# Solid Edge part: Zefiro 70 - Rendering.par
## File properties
Title: Zefiro 70
Author: DESYS
Template: Normal.par
Last saved by: i.fialdini
Revision: 39
Application: Solid Edge
Tipo di contenuto documento: 0
Precisione: 0.990
Document Number: 8206
Revision: 0
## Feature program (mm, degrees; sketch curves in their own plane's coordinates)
lofted protrusion "unnamed LoftedProtrusion 1"
sketch for "unnamed Cutout 1" plane through (0, 0, 0) normal (1, 0, 0) x-axis (0, 1, 0)
  arc centre (0, 843.7224) radius 911.7224 from (-345.5, 0) to (345.5, 0) ccw
extrude "unnamed Cutout 1" cut through
thinwall "unnamed Thinwall 1"
sketch for "ExtrudedProtrusion_1" plane through (0, 0, -158) normal (0, 0, -1) x-axis (0, 1, 0)
extrude "ExtrudedProtrusion_1" add finite 10 along +normal
sketch for "ScavoEstrusione_2" plane through (0, 0, -168) normal (0, 0, -1) x-axis (0, 1, 0)
extrude "ScavoEstrusione_2" cut finite 15 along -normal
sketch for "ExtrudedProtrusion_6" plane through (-0.0005, 0, -153) normal (0, 0, -1) x-axis (0, 1, 0)
extrude "ExtrudedProtrusion_6" add finite 30 along +normal
sketch for "Foro_1" plane through (0, 0, -183) normal (0, 0, -1) x-axis (0, 1, 0)
  hole centre (0, 0) bore radius 25
hole "Foro_1" diameter 50 through
boolean "unnamed Boolean 1"
fillet "Rotondo_15" radius 10
fillet "Rotondo_1" radius 5
fillet "Rotondo_5" radius 10
fillet "Rotondo_3" radius 50
fillet "Rotondo_22" radius 40
fillet "Rotondo_23" radius 5
sketch for "unnamed RevolvedProtrusion 1" plane through (0, 0, 0) normal (1, 0, 0) x-axis (0, 1, 0)
revolve "unnamed RevolvedProtrusion 1" add full turn 360 deg
fillet "Rotondo_24" radius 5
fillet "Rotondo_25" radius 7
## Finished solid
Body 1: sheet body, 1 face, 2 edges, 0 vertices.
  Faces by surface: spline 1
  Edges by curve: circle 1, intersection 1
Body 2: solid body, 17 faces, 18 edges, 3 vertices.
  Faces by surface: blend 6, plane 4, cylinder 2, spline 2, cone 1, swept 1, torus 1
  Edges by curve: intersection 12, circle 5, ellipse 1
Bounding box of the edges (mm; curved faces can reach further): 357.510 x 680.842 x 178.409, from (-178.6113, -340.4187, -183) to (178.8991, 340.4235, -4.5911).
Cylindrical faces by radius (mm): R25 x1, R911.7224 x1
Conical faces (half-angle, radius in mm at the cone's reference point): 38.6598 deg R35 x1
Toroidal faces (ring radius, tube radius in mm): R30 r5 x1
Planar faces by outward normal: -z 4
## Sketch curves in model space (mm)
arc centre (25, 0, 23.7635) radius 171.7635 from (170.197, 0, -68) through (107.8887, 0, -126.6764) to (25, 0, -148)
arc centre (-25, 0, 23.7635) radius 171.7635 from (-170.197, 0, -68) through (-107.8887, 0, -126.6764) to (-25, 0, -148)
arc centre (0, -25, 254.0829) radius 402.0829 from (0, -25, -148) through (0, -194.3662, -110.5892) to (0, -332.2159, -5.3184)
arc centre (0, 25, 254.0829) radius 402.0829 from (0, 332.2159, -5.3184) through (0, 194.3662, -110.5892) to (0, 25, -148)
arc centre (34.1412, 0, -35.003) radius 150 from (180, 0, 0) through (174.3705, 0, -88.2546) to (120, 0, -158)
arc centre (-34.1412, 0, -35.003) radius 150 from (-180, 0, 0) through (-174.3705, 0, -88.2546) to (-120, 0, -158)
arc centre (0, 69.0627, 116.5435) radius 300 from (0, 345.5, 0) through (0, 282.8795, -93.8902) to (0, 190, -158)
arc centre (0, -69.0627, 116.5435) radius 300 from (0, -345.5, 0) through (0, -282.8795, -93.8902) to (0, -190, -158)
ellipse centre (0, 0, -158) radii 190, 120
ellipse centre (0, 0, 0) radii 345.5, 180
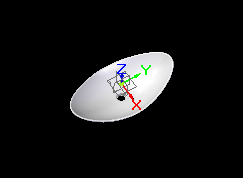
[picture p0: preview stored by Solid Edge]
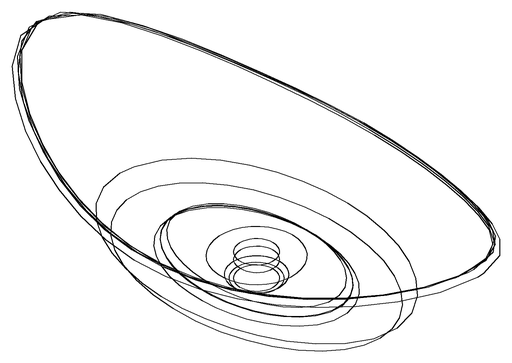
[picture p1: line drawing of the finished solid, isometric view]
